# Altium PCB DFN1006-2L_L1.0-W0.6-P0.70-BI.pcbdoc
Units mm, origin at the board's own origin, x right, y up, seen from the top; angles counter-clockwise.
Board outline 14.1 x 13.54 mm, 2 copper layers (Top Layer, Bottom Layer), stack 0 mm thick; 1 components, 0 nets, 2 pads, 0 vias.
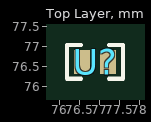
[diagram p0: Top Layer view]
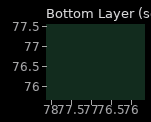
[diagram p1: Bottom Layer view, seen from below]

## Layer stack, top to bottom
Top Layer: signal copper (thickness not stored)
Bottom Layer: signal copper (thickness not stored)

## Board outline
83.95,69.85 69.85,69.85 69.85,83.39 83.95,83.39

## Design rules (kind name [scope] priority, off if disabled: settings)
PasteMaskExpansion "Paste Mask Expansion" [All] p1: expansion=0
SolderMaskExpansion "Solder Mask Expansion" [IsVia] p1: expansion=-25.4 istentingtop=TRUE
SolderMaskExpansion "Solder Mask Expansion" [All] p2: expansion=0.051 istentingtop=FALSE

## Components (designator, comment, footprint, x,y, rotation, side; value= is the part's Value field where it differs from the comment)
U? "" DFN1006-2L_L1.0-W0.6-P0.70-BI 76.9,76.62 r0 top

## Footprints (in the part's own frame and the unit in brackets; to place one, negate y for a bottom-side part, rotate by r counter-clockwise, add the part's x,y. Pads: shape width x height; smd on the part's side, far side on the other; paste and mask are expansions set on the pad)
DFN1006-2L_L1.0-W0.6-P0.70-BI [mm]
  rect 0.4x0.6 smd: 1(-0.325,0) 2(0.325,0)
  silkscreen extent -0.7,-0.42 0.7,0.42

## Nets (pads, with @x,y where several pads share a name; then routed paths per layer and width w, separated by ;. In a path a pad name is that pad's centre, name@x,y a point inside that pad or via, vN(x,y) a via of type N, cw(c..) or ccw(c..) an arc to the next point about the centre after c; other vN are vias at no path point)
pads on no net: U?.1 U?.2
